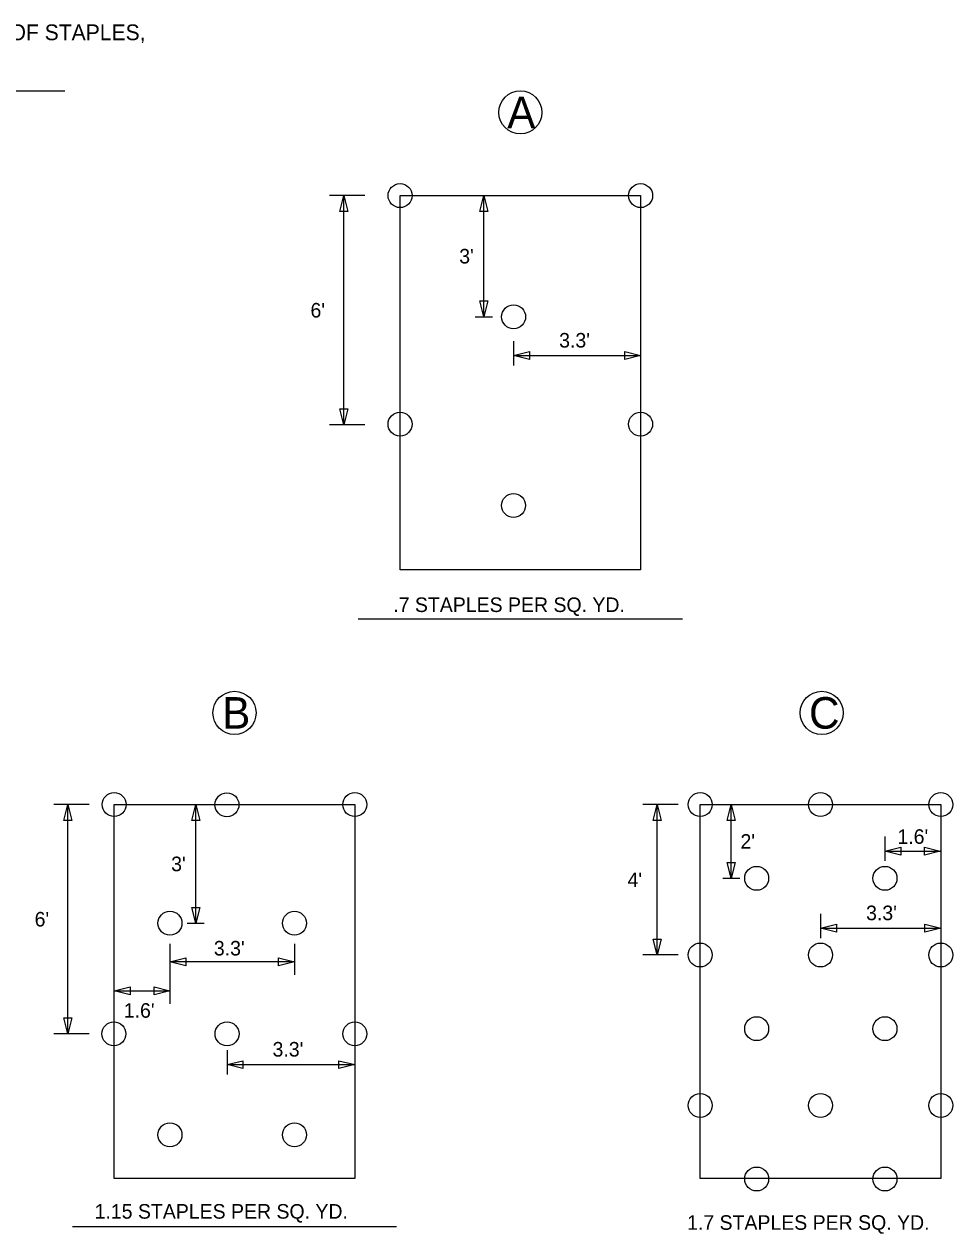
# Model space of a CAD drawing. Extents: x 27123946 to 27124151, y 1145898 to 1146027.
# Drawn here: x 27124100.1 to 27124148.9, y 1145962.5 to 1146026 of the extents above; entities that cross this region are included whole.
import ezdxf

# ---------------------------------------------------------------- set-up
doc = ezdxf.new("R2010")
doc.units = 0
for name, color, linetype in [('C-PVMT', 7, 'Continuous'), ('Default', 7, 'Continuous'), ('G-ANNO-TEXT', 7, 'Continuous'), ('L-MISC-LINE', 7, 'Continuous'), ('L-SITE-SOIL', 7, 'Continuous')]:
    doc.layers.add(name, color=color, linetype=linetype)

msp = doc.modelspace()

# ---------------------------------------------------------------- linework, layer by layer
at = {"layer": 'C-PVMT'}
msp.add_line((27124087.272, 1146022.474), (27124102.27, 1146022.474), dxfattribs=at)
at = {"layer": 'Default'}
for p, q in [((27124135.93, 1145984.995), (27124137.831, 1145984.995)), ((27124148.258, 1145980.139), (27124148.258, 1145976.505))]:
    msp.add_line(p, q, dxfattribs=at)
for points in [[(27124119.872, 1146016.97), (27124132.5, 1146016.97), (27124132.5, 1145997.329), (27124119.872, 1145997.329)], [(27124135.63, 1145984.995), (27124148.258, 1145984.995), (27124148.258, 1145965.354), (27124135.63, 1145965.354)]]:
    msp.add_lwpolyline(points, close=True, dxfattribs=at)
at = {"layer": 'G-ANNO-TEXT'}
for p, q in [((27124118.024, 1146016.97), (27124116.175, 1146016.97)), ((27124116.916, 1146004.934), (27124116.916, 1146016.97)), ((27124124.268, 1146010.608), (27124124.268, 1146016.97)), ((27124123.817, 1146010.608), (27124124.718, 1146010.608)), ((27124125.832, 1146009.332), (27124125.832, 1146008.055)), ((27124125.832, 1146008.57), (27124132.5, 1146008.57)), ((27124118.024, 1146004.934), (27124116.175, 1146004.934)), ((27124117.678, 1145994.755), (27124134.695, 1145994.755)), ((27124103.543, 1145984.995), (27124101.695, 1145984.995)), ((27124102.436, 1145972.959), (27124102.436, 1145984.995)), ((27124109.144, 1145978.765), (27124109.144, 1145984.995)), ((27124134.469, 1145984.995), (27124132.62, 1145984.995)), ((27124133.361, 1145977.098), (27124133.361, 1145984.995)), ((27124137.258, 1145981.127), (27124137.258, 1145984.995)), ((27124145.326, 1145983.313), (27124145.326, 1145982.036)), ((27124145.326, 1145982.551), (27124148.258, 1145982.551)), ((27124136.808, 1145981.127), (27124137.708, 1145981.127)), ((27124141.944, 1145979.264), (27124141.944, 1145977.987)), ((27124108.694, 1145978.765), (27124109.594, 1145978.765)), ((27124141.944, 1145978.502), (27124148.258, 1145978.502)), ((27124107.793, 1145977.683), (27124107.793, 1145974.539)), ((27124114.329, 1145977.683), (27124114.327, 1145976.059)), ((27124114.328, 1145976.736), (27124107.791, 1145976.736)), ((27124134.469, 1145977.098), (27124132.62, 1145977.098)), ((27124104.865, 1145975.212), (27124107.793, 1145975.212)), ((27124103.543, 1145972.959), (27124101.695, 1145972.959)), ((27124110.788, 1145972.103), (27124110.788, 1145970.826)), ((27124110.788, 1145971.341), (27124117.493, 1145971.341)), ((27124102.67, 1145962.846), (27124119.688, 1145962.846))]:
    msp.add_line(p, q, dxfattribs=at)
for points in [[(27124116.708, 1146016.137), (27124116.916, 1146016.97), (27124117.125, 1146016.137)], [(27124124.059, 1146016.137), (27124124.268, 1146016.97), (27124124.476, 1146016.137)], [(27124124.476, 1146011.442), (27124124.268, 1146010.608), (27124124.059, 1146011.442)], [(27124126.665, 1146008.361), (27124125.832, 1146008.57), (27124126.665, 1146008.778)], [(27124131.667, 1146008.778), (27124132.5, 1146008.57), (27124131.667, 1146008.361)], [(27124117.125, 1146005.767), (27124116.916, 1146004.934), (27124116.708, 1146005.767)], [(27124102.227, 1145984.161), (27124102.436, 1145984.995), (27124102.644, 1145984.161)], [(27124108.935, 1145984.161), (27124109.144, 1145984.995), (27124109.352, 1145984.161)], [(27124133.153, 1145984.161), (27124133.361, 1145984.995), (27124133.57, 1145984.161)], [(27124137.05, 1145984.161), (27124137.258, 1145984.995), (27124137.466, 1145984.161)], [(27124146.159, 1145982.342), (27124145.326, 1145982.551), (27124146.159, 1145982.759)], [(27124147.398, 1145982.759), (27124148.231, 1145982.551), (27124147.398, 1145982.342)], [(27124137.466, 1145981.96), (27124137.258, 1145981.127), (27124137.05, 1145981.96)], [(27124109.352, 1145979.598), (27124109.144, 1145978.765), (27124108.935, 1145979.598)], [(27124142.777, 1145978.294), (27124141.944, 1145978.502), (27124142.777, 1145978.71)], [(27124147.425, 1145978.71), (27124148.258, 1145978.502), (27124147.425, 1145978.294)], [(27124133.57, 1145977.931), (27124133.361, 1145977.098), (27124133.153, 1145977.931)], [(27124108.624, 1145976.527), (27124107.791, 1145976.736), (27124108.624, 1145976.944)], [(27124113.494, 1145976.944), (27124114.328, 1145976.736), (27124113.494, 1145976.527)], [(27124105.698, 1145975.004), (27124104.865, 1145975.212), (27124105.698, 1145975.42)], [(27124106.96, 1145975.42), (27124107.793, 1145975.212), (27124106.96, 1145975.004)], [(27124102.644, 1145973.792), (27124102.436, 1145972.959), (27124102.227, 1145973.792)], [(27124111.621, 1145971.133), (27124110.788, 1145971.341), (27124111.621, 1145971.549)], [(27124116.66, 1145971.549), (27124117.493, 1145971.341), (27124116.66, 1145971.133)]]:
    msp.add_lwpolyline(points, close=True, dxfattribs=at)
for centre in [(27124126.186, 1146021.339), (27124111.179, 1145989.81), (27124142.005, 1145989.81)]:
    msp.add_circle(centre, 1.132, dxfattribs=at)
at = {"layer": 'L-MISC-LINE'}
for centre in [(27124119.872, 1146016.97), (27124132.5, 1146016.97), (27124125.832, 1146010.608), (27124119.87, 1146004.971), (27124132.498, 1146004.971), (27124125.828, 1146000.7), (27124104.865, 1145984.995), (27124110.784, 1145984.987), (27124117.493, 1145984.995), (27124135.63, 1145984.995), (27124141.944, 1145984.995), (27124148.258, 1145984.995), (27124138.591, 1145981.123), (27124145.326, 1145981.123), (27124107.793, 1145978.765), (27124114.331, 1145978.765), (27124135.626, 1145977.098), (27124141.944, 1145977.098), (27124148.254, 1145977.098), (27124104.849, 1145972.959), (27124110.788, 1145972.959), (27124117.498, 1145972.959), (27124138.591, 1145973.229), (27124145.326, 1145973.229), (27124135.63, 1145969.2), (27124141.944, 1145969.2), (27124148.254, 1145969.2), (27124107.793, 1145967.657), (27124114.331, 1145967.657), (27124138.591, 1145965.336), (27124145.326, 1145965.336)]:
    msp.add_circle(centre, 0.629, dxfattribs=at)
at = {"layer": 'L-SITE-SOIL'}
msp.add_lwpolyline([(27124104.865, 1145984.995), (27124117.493, 1145984.995), (27124117.493, 1145965.354), (27124104.865, 1145965.354)], close=True, dxfattribs=at)

# ---------------------------------------------------------------- texts
at = {"layer": 'G-ANNO-TEXT'}
for s, height, p in [('1 ROW OF STAPLES,', 0.828, (27124095.435, 1146025.131)), ('A', 1.656, (27124125.498, 1146020.511)), ("3'", 0.7645, (27124122.979, 1146013.407)), ("6'", 0.7645, (27124115.169, 1146010.57)), ("3.3'", 0.7645, (27124128.223, 1146008.993)), ('.7 STAPLES PER SQ. YD.', 0.7645, (27124119.515, 1145995.106)), ('B', 1.656, (27124110.533, 1145988.982)), ('C', 1.656, (27124141.34, 1145988.982)), ("1.6'", 0.7645, (27124145.98, 1145982.934)), ("2'", 0.7645, (27124137.74, 1145982.678)), ("3'", 0.7645, (27124107.856, 1145981.497)), ("4'", 0.7645, (27124131.811, 1145980.664)), ("6'", 0.7645, (27124100.688, 1145978.594)), ("3.3'", 0.7645, (27124144.335, 1145978.926)), ("3.3'", 0.7645, (27124110.098, 1145977.072)), ("1.6'", 0.7645, (27124105.368, 1145973.803)), ("3.3'", 0.7645, (27124113.179, 1145971.765)), ('1.15 STAPLES PER SQ. YD.', 0.7645, (27124103.838, 1145963.253)), ('1.7 STAPLES PER SQ. YD.', 0.7645, (27124134.938, 1145962.668))]:
    msp.add_text(s, height=height, dxfattribs=at).set_placement(p)

doc.saveas('drawing.dxf')
